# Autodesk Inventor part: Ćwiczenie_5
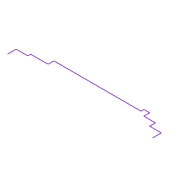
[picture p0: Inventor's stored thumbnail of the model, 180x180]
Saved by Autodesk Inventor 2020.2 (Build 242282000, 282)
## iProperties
Created: 2005-01
Part Number: Ćwiczenie_5
Document SubType Name: Modeling
Designer: F.Stasiak
Manufacturer: Standard
Standards Organization: Custom
Density: 1 g/cm^3
Material: Ogólny
Appearance: Domyślna
Manager: www.cadconsulting.pl
Company: Fabian Stasiak CAD Consulting
Author: F.Stasiak
Subject: Zbiór ćwiczeń. Autodesk Inventor 2020. Kurs podstawowy
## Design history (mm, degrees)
sketch "Szkic1"
  geometry: L1 (98.674, 95.628)-(98.674, 110.628); L2 (98.674, 110.628)-(118.674, 110.628); L3 (118.674, 110.628)-(118.674, 115.628); L4 (118.674, 115.628)-(148.674, 115.628); L5 (148.674, 115.628)-(148.674, 125.628); L6 (148.674, 125.628)-(298.674, 125.628); L7 (298.674, 125.628)-(298.674, 130.628); L8 (298.674, 130.628)-(308.674, 130.628); L9 (308.674, 130.628)-(308.674, 120.628); L10 (308.674, 120.628)-(328.674, 120.628); L11 (328.674, 120.628)-(328.674, 110.628); L12 (328.674, 110.628)-(348.674, 110.628); L13 (348.674, 110.628)-(348.674, 95.628)
  constraints: 26 end point, 10 parallel, 1 collinear, 1 perpendicular, 1 vertical
node "Korpusy bryłowe"
node "Korpusy powierzchniowe"
